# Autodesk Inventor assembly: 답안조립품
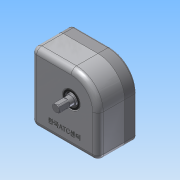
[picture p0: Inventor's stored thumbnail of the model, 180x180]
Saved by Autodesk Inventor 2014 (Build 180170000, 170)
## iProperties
Created: 2015-11
Part Number: 답안조립품
Document SubType Name: Assembly
Designer: net
Author: net
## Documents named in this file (10)
- C:\Users\net\Desktop\Inventor2급-박유나\답안조립품.iam
- C:\Users\net\Desktop\Inventor2급-박유나\본체.ipt
- C:\Users\net\Desktop\Inventor2급-박유나\베어링 6002.ipt
- C:\Users\net\Desktop\Inventor2급-박유나\베어링 6001.ipt
- C:\Users\net\Desktop\Inventor2급-박유나\편심 축.ipt
- C:\Users\net\Desktop\Inventor2급-박유나\로드 축.ipt
- C:\Users\net\Desktop\Inventor2급-박유나\로드.ipt
- C:\Users\net\Desktop\Inventor2급-박유나\앞커버.ipt
- C:\Users\net\Desktop\Inventor2급-박유나\오일실 15 x 25.ipt
- C:\Users\net\Desktop\Inventor2급-박유나\오일실 12 x 22.ipt
